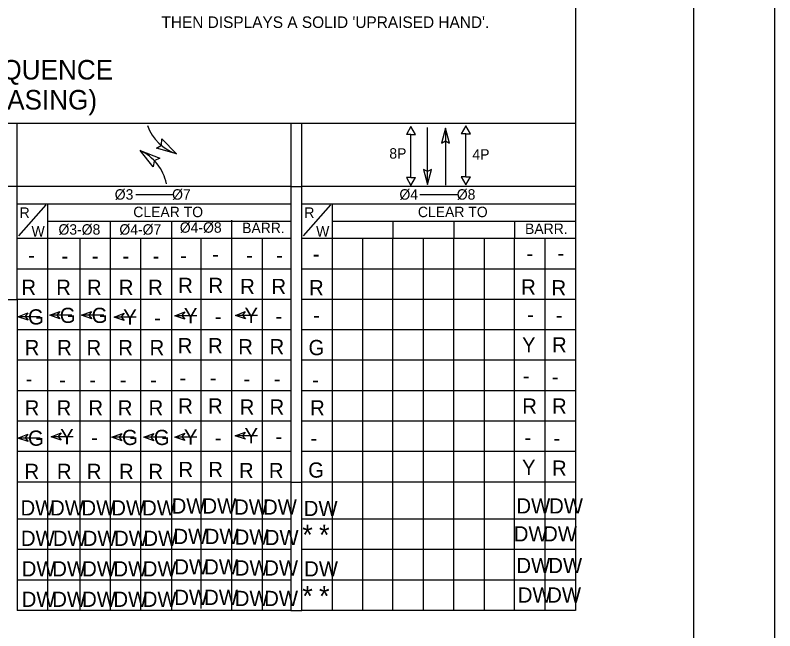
# Model space of a CAD drawing. Extents: x 0 to 3.01, y -0.05 to 1.83.
# Drawn here: x 2.6475 to 3, y 1.2662 to 1.5516 of the extents above; entities that cross this region are included whole.
import ezdxf

# ---------------------------------------------------------------- set-up
doc = ezdxf.new("R2010")
doc.units = 0
for name, color, linetype in [('RD_SHT_IplotShp', 7, 'Continuous'), ('TR_TS_Border', 7, 'Continuous'), ('TR_TS_Phase1', 7, 'Continuous'), ('TR_TS_Phase2', 7, 'Continuous'), ('TR_TS_Phase3', 7, 'Continuous'), ('TR_TS_Phase4', 7, 'Continuous'), ('TR_TS_Phase5', 7, 'Continuous'), ('TR_TS_Phase6', 7, 'Continuous'), ('TR_TS_Phase7', 7, 'Continuous'), ('TR_TS_Phase8', 7, 'Continuous')]:
    doc.layers.add(name, color=color, linetype=linetype)

msp = doc.modelspace()

# ---------------------------------------------------------------- linework, layer by layer
at = {"layer": 'RD_SHT_IplotShp'}
msp.add_lwpolyline([(-3.9736429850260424e-10, -8.265177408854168e-09), (3.0000020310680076, -8.265177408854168e-09), (3.0000020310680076, 1.8333311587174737), (-3.9736429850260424e-10, 1.8333311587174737)], close=True, dxfattribs=at)
at = {"layer": 'TR_TS_Border'}
for p, q in [((3.0000020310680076, -8.265177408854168e-09), (3.0000020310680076, 1.8333311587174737)), ((2.9623464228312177, 0.04746643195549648), (2.9623464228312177, 1.775395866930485)), ((2.9074767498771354, 1.7049511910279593), (2.9074766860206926, 1.275593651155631)), ((2.907476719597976, 1.5013454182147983), (2.2983738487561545, 1.5013454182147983)), ((2.6483232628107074, 1.4198639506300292), (2.6483232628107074, 1.5013455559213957)), ((2.7753427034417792, 1.5013455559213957), (2.7753427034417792, 1.27559374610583)), ((2.780404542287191, 1.5013455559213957), (2.780404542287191, 1.27559374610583)), ((2.6483232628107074, 1.4722744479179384), (2.638252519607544, 1.4722744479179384)), ((2.7753427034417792, 1.4722744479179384), (2.6483232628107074, 1.4722744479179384)), ((2.7753427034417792, 1.4722744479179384), (2.780404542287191, 1.4722744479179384)), ((2.907476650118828, 1.4722744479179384), (2.780404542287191, 1.4722744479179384)), ((2.7034480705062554, 1.468530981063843), (2.7205960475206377, 1.468530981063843)), ((2.8352356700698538, 1.468530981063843), (2.8529832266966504, 1.468530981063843)), ((2.6483232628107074, 1.4642071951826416), (2.7753427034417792, 1.4642071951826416)), ((2.649167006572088, 1.4492854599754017), (2.661821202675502, 1.4637328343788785)), ((2.6624014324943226, 1.4642071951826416), (2.6624014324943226, 1.27559374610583)), ((2.780404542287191, 1.4642071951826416), (2.907476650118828, 1.4642071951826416)), ((2.781248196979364, 1.4492854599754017), (2.7939024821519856, 1.4637328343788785)), ((2.794535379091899, 1.4642071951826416), (2.794535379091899, 1.27559374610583)), ((2.6624014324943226, 1.4561402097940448), (2.7753427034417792, 1.4561402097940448)), ((2.6915352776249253, 1.4561402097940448), (2.6915352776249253, 1.27559374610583)), ((2.720037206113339, 1.4562394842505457), (2.720037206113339, 1.2756930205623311)), ((2.7479278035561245, 1.4565373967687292), (2.7479278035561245, 1.275990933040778)), ((2.794535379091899, 1.4561402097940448), (2.907476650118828, 1.4561402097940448)), ((2.8227442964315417, 1.4561402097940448), (2.8227442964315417, 1.4480727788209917)), ((2.8510059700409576, 1.4561402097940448), (2.8510059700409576, 1.4480727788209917)), ((2.8792152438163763, 1.4561402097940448), (2.8792152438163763, 1.4480727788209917)), ((2.7753427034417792, 1.4480727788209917), (2.6483232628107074, 1.4480727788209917)), ((2.6774043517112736, 1.4480727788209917), (2.6774043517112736, 1.27559374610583)), ((2.7056134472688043, 1.4480727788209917), (2.7056134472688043, 1.27559374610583)), ((2.7336929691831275, 1.4480727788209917), (2.7336929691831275, 1.276487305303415)), ((2.7620583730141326, 1.4480727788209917), (2.7620583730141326, 1.275990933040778)), ((2.907476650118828, 1.4480727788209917), (2.780404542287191, 1.4480727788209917)), ((2.808666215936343, 1.4480727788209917), (2.808666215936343, 1.27559374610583)), ((2.8227442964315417, 1.27559374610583), (2.8227442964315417, 1.4480727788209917)), ((2.8368751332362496, 1.4480727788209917), (2.8368751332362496, 1.27559374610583)), ((2.8510059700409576, 1.27559374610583), (2.8510059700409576, 1.4480727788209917)), ((2.8651368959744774, 1.4480727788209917), (2.8651368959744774, 1.27559374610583)), ((2.8792152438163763, 1.27559374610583), (2.8792152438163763, 1.4480727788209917)), ((2.89334572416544, 1.4480727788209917), (2.89334572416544, 1.27559374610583)), ((2.7753427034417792, 1.433941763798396), (2.6483232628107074, 1.433941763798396)), ((2.907476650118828, 1.433941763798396), (2.780404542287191, 1.433941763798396)), ((2.638252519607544, 1.4198639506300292), (2.6483232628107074, 1.4198639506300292)), ((2.7753427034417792, 1.4198639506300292), (2.6483232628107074, 1.4198639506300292)), ((2.6483232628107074, 1.4198639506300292), (2.6483232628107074, 1.27559374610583)), ((2.907476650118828, 1.4198639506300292), (2.780404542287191, 1.4198639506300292)), ((2.7753427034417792, 1.405733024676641), (2.6483232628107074, 1.405733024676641)), ((2.907476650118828, 1.405733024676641), (2.780404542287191, 1.405733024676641)), ((2.7753427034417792, 1.3916020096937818), (2.6483232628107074, 1.3916020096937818)), ((2.907476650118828, 1.3916020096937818), (2.780404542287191, 1.3916020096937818)), ((2.7753427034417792, 1.3775241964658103), (2.6483232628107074, 1.3775241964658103)), ((2.907476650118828, 1.3775241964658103), (2.780404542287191, 1.3775241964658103)), ((2.7753427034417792, 1.3633932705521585), (2.6483232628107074, 1.3633932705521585)), ((2.907476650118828, 1.3633932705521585), (2.780404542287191, 1.3633932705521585)), ((2.7753427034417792, 1.3492622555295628), (2.6483232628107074, 1.3492622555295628)), ((2.907476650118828, 1.3492622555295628), (2.780404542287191, 1.3492622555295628)), ((2.7753427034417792, 1.3351314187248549), (2.6483232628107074, 1.3351314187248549)), ((2.7753427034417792, 1.3351314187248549), (2.780404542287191, 1.3351314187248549)), ((2.907476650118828, 1.3351314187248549), (2.780404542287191, 1.3351314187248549)), ((2.775416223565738, 1.3179863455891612), (2.6483966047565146, 1.3179863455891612)), ((2.9075500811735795, 1.3179863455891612), (2.780477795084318, 1.3179863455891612)), ((2.775416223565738, 1.3038554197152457), (2.6483966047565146, 1.3038554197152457)), ((2.9075500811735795, 1.3038554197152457), (2.780477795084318, 1.3038554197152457)), ((2.775416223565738, 1.2897245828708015), (2.6483966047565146, 1.2897245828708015)), ((2.9075500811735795, 1.2897245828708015), (2.780477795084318, 1.2897245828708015)), ((2.775416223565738, 1.27559374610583), (2.6483966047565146, 1.27559374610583)), ((2.775416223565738, 1.27559374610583), (2.780477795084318, 1.27559374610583)), ((2.907476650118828, 1.27559374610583), (2.780477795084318, 1.27559374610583))]:
    msp.add_line(p, q, dxfattribs=at)
at = {"layer": 'TR_TS_Phase3'}
for p, q in [((2.7129855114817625, 1.489924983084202), (2.7153600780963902, 1.4914362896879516)), ((2.7153600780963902, 1.4914362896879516), (2.715504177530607, 1.4942426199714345)), ((2.715504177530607, 1.4942426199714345), (2.722340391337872, 1.4874063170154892)), ((2.722340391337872, 1.4874063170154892), (2.7129855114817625, 1.489924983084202)), ((2.6634985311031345, 1.4125119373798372), (2.6681329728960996, 1.4142745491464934)), ((2.6681329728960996, 1.4142745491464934), (2.6668036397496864, 1.4125706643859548)), ((2.67829194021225, 1.4125119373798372), (2.6829263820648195, 1.4142745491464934)), ((2.6829263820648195, 1.4142745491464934), (2.681597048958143, 1.4125706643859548)), ((2.7215234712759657, 1.412266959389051), (2.726157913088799, 1.4140297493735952)), ((2.726157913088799, 1.4140297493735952), (2.7248285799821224, 1.4123256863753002)), ((2.7496479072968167, 1.412454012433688), (2.754282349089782, 1.4142166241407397)), ((2.754282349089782, 1.4142166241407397), (2.7529530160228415, 1.4125127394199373)), ((2.6487489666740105, 1.4117958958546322), (2.6533833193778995, 1.4135586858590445)), ((2.659010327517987, 1.4117958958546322), (2.6487489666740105, 1.4117958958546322)), ((2.6534273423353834, 1.4101873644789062), (2.6487489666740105, 1.4117958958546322)), ((2.6533833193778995, 1.4135586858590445), (2.6520540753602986, 1.4118546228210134)), ((2.6520540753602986, 1.4118546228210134), (2.6534273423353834, 1.4101873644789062)), ((2.6737599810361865, 1.4125119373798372), (2.6634985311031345, 1.4125119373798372)), ((2.6681769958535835, 1.4109034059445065), (2.6634985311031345, 1.4125119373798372)), ((2.6668036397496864, 1.4125706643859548), (2.6681769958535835, 1.4109034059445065)), ((2.6885533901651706, 1.4125119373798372), (2.67829194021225, 1.4125119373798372)), ((2.682970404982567, 1.4109034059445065), (2.67829194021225, 1.4125119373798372)), ((2.681597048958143, 1.4125706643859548), (2.682970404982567, 1.4109034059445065)), ((2.6933708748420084, 1.4116336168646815), (2.6980052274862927, 1.4133964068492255)), ((2.7036318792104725, 1.4116336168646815), (2.6933708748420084, 1.4116336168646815)), ((2.698049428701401, 1.4100252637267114), (2.6933708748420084, 1.4116336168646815)), ((2.6980052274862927, 1.4133964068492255), (2.6966759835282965, 1.4116924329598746)), ((2.6966759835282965, 1.4116924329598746), (2.698049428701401, 1.4100252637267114)), ((2.7317845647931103, 1.412266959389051), (2.7215234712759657, 1.412266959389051)), ((2.726201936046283, 1.410658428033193), (2.7215234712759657, 1.412266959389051)), ((2.7248285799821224, 1.4123256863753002), (2.726201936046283, 1.410658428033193)), ((2.759909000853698, 1.412454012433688), (2.7496479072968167, 1.412454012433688)), ((2.7543263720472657, 1.4108454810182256), (2.7496479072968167, 1.412454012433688)), ((2.7529530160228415, 1.4125127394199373), (2.7543263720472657, 1.4108454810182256))]:
    msp.add_line(p, q, dxfattribs=at)
msp.add_arc((2.729174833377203, 1.5078541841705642), 0.021617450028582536, 200.13881944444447, 251.63656666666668, dxfattribs=at)
at = {"layer": 'TR_TS_Phase4'}
for p, q in [((2.847129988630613, 1.499277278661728), (2.8452641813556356, 1.4923477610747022)), ((2.847129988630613, 1.499277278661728), (2.847129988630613, 1.4728914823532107)), ((2.8489957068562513, 1.4923477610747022), (2.847129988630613, 1.499277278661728)), ((2.856627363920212, 1.5003211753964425), (2.854495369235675, 1.4966489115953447)), ((2.858759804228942, 1.4966489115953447), (2.856627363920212, 1.5003211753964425)), ((2.856627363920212, 1.4966489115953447), (2.854495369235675, 1.4966489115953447)), ((2.856627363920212, 1.4766825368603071), (2.856627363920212, 1.4966489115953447)), ((2.856627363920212, 1.4966489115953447), (2.858759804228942, 1.4966489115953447)), ((2.8452641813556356, 1.4923477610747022), (2.847129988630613, 1.4933072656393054)), ((2.847129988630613, 1.4933072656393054), (2.8489957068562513, 1.4923477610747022)), ((2.856627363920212, 1.4766110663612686), (2.8544951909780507, 1.4766110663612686)), ((2.8544951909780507, 1.4766110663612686), (2.856627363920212, 1.4729388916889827)), ((2.856627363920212, 1.4729388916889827), (2.8587596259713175, 1.4766110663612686)), ((2.856627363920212, 1.4766110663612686), (2.8587596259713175, 1.4766110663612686))]:
    msp.add_line(p, q, dxfattribs=at)
at = {"layer": 'TR_TS_Phase7'}
for p, q in [((2.7115733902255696, 1.4813676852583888), (2.7055217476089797, 1.4889076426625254)), ((2.7055217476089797, 1.4889076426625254), (2.714546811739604, 1.4853856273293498)), ((2.7120218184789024, 1.4841416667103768), (2.7115733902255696, 1.4813676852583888)), ((2.714546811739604, 1.4853856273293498), (2.7120218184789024, 1.4841416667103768)), ((2.6487489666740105, 1.355571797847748), (2.6533833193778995, 1.3573344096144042)), ((2.6533833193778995, 1.3573344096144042), (2.6520540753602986, 1.3556305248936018)), ((2.6641120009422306, 1.3561904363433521), (2.668746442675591, 1.3579530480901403)), ((2.668746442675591, 1.3579530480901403), (2.6674171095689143, 1.3562492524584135)), ((2.692367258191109, 1.3558971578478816), (2.697001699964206, 1.357659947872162)), ((2.697001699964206, 1.357659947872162), (2.6956723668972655, 1.355955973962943)), ((2.707160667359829, 1.3558971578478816), (2.711795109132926, 1.357659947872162)), ((2.711795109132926, 1.357659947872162), (2.710465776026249, 1.355955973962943)), ((2.7215234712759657, 1.356042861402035), (2.726157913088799, 1.3578054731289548)), ((2.726157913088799, 1.3578054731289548), (2.7248285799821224, 1.356101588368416)), ((2.7496428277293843, 1.3565876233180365), (2.7542772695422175, 1.3583502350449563)), ((2.7542772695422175, 1.3583502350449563), (2.752947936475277, 1.3566464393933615)), ((2.659010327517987, 1.355571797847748), (2.6487489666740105, 1.355571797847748)), ((2.6534273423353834, 1.3539632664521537), (2.6487489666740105, 1.355571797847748)), ((2.6520540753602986, 1.3556305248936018), (2.6534273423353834, 1.3539632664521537)), ((2.6743730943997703, 1.3561904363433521), (2.6641120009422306, 1.3561904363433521)), ((2.6687904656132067, 1.3545819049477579), (2.6641120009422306, 1.3561904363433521)), ((2.6674171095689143, 1.3562492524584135), (2.6687904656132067, 1.3545819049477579)), ((2.7026287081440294, 1.3558971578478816), (2.692367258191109, 1.3558971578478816)), ((2.6970457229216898, 1.3542886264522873), (2.692367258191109, 1.3558971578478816)), ((2.6956723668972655, 1.355955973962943), (2.6970457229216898, 1.3542886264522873)), ((2.717421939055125, 1.3558971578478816), (2.707160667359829, 1.3558971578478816)), ((2.711839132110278, 1.3542886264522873), (2.707160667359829, 1.3558971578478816)), ((2.710465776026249, 1.355955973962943), (2.711839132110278, 1.3542886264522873)), ((2.7317845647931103, 1.356042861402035), (2.7215234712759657, 1.356042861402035)), ((2.726201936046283, 1.3544343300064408), (2.7215234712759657, 1.356042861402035)), ((2.7248285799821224, 1.356101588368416), (2.726201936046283, 1.3544343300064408)), ((2.7599039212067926, 1.3565876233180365), (2.7496428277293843, 1.3565876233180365)), ((2.7543214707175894, 1.3549790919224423), (2.7496428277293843, 1.3565876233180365)), ((2.752947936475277, 1.3566464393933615), (2.7543214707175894, 1.3549790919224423))]:
    msp.add_line(p, q, dxfattribs=at)
msp.add_arc((2.6964534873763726, 1.4692224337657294), 0.02161745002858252, 11.426533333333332, 65.38743333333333, dxfattribs=at)
at = {"layer": 'TR_TS_Phase8'}
for p, q in [((2.831158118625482, 1.5000583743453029), (2.8290260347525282, 1.4963861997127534)), ((2.8332904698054, 1.4963861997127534), (2.831158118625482, 1.5000583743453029)), ((2.8388868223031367, 1.4731735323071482), (2.8388868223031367, 1.4995593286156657)), ((2.831158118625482, 1.4963861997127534), (2.8290260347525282, 1.4963861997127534)), ((2.831158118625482, 1.476419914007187), (2.831158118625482, 1.4963861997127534)), ((2.831158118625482, 1.4963861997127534), (2.8332904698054, 1.4963861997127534)), ((2.8388868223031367, 1.4791435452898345), (2.837021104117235, 1.4801030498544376)), ((2.837021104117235, 1.4801030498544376), (2.8388868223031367, 1.4731735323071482)), ((2.8407525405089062, 1.4801030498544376), (2.8388868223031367, 1.4791435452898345)), ((2.8388868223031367, 1.4731735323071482), (2.8407525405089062, 1.4801030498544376)), ((2.831158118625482, 1.4763484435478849), (2.8290258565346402, 1.4763484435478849)), ((2.8290258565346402, 1.4763484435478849), (2.831158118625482, 1.4726762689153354)), ((2.831158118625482, 1.4726762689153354), (2.833290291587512, 1.4763484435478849)), ((2.831158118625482, 1.4763484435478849), (2.833290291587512, 1.4763484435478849))]:
    msp.add_line(p, q, dxfattribs=at)

# ---------------------------------------------------------------- texts
at = {"layer": 'TR_TS_Border'}
for s, height, p in [("THEN DISPLAYS A SOLID 'UPRAISED HAND'.", 0.005346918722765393, (2.7153579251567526, 1.5457078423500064)), ('SIGNAL DISPLAY SEQUENCE', 0.009062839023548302, (2.5225272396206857, 1.5218125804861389)), ('(PREFERENTIAL PHASING)', 0.009062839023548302, (2.5279138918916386, 1.5078981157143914))]:
    msp.add_text(s, height=height, dxfattribs=at).set_placement(p)
for s, height, p in [('Ø3          Ø7', 0.004840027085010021, (2.6936825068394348, 1.466104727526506)), ('Ø4          Ø8', 0.004840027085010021, (2.8258007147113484, 1.466104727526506)), ('R', 0.004840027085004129, (2.6495210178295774, 1.457668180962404)), ('CLEAR TO', 0.004840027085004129, (2.702291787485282, 1.4579846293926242)), ('R', 0.004840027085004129, (2.7816552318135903, 1.457668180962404)), ('CLEAR TO', 0.004840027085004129, (2.8343729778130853, 1.4579846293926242)), ('W', 0.004840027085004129, (2.6550681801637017, 1.4489682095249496)), ('Ø3-Ø8', 0.004840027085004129, (2.6675674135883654, 1.4498646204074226)), ('Ø4-Ø7', 0.004840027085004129, (2.695846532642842, 1.4498646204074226)), ('Ø4-Ø8', 0.004840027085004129, (2.723873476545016, 1.4507581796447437)), ('BARR.', 0.004840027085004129, (2.7528034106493, 1.4505781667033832)), ('W', 0.004840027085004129, (2.7871494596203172, 1.4489682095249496)), ('BARR.', 0.004840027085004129, (2.8840906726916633, 1.4501810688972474))]:
    msp.add_text(s, height=height, rotation=360, dxfattribs=at).set_placement(p)
at = {"layer": 'TR_TS_Phase1'}
for p in [(2.6534825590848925, 1.4368748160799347), (2.668997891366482, 1.436473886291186), (2.683032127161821, 1.436473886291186), (2.6972190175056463, 1.436473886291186), (2.711253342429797, 1.436473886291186), (2.7239767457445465, 1.4367453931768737), (2.7389060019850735, 1.437367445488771), (2.7545894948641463, 1.4368709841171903), (2.7686236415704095, 1.4368709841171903), (2.7856278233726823, 1.4374106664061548), (2.8847434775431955, 1.4375876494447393), (2.899194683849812, 1.43781346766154)]:
    msp.add_text('-', height=0.007050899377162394, dxfattribs=at).set_placement(p)
at = {"layer": 'TR_TS_Phase2'}
for s, p in [('R', (2.6503341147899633, 1.4219349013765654)), ('R', (2.6664964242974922, 1.4219349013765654)), ('R', (2.6807937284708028, 1.4219349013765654)), ('R', (2.695531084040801, 1.4219349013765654)), ('R', (2.7091685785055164, 1.4219349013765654)), ('R', (2.723111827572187, 1.4228284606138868)), ('R', (2.7371892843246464, 1.4228284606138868)), ('R', (2.7518692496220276, 1.4223319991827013)), ('R', (2.7663863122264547, 1.4223319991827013)), ('DW', (2.6499532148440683, 1.3196504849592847)), ('DW', (2.6636959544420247, 1.3196504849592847)), ('DW', (2.6782131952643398, 1.3196504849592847)), ('DW', (2.692070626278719, 1.3196504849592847)), ('DW', (2.7063679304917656, 1.3196504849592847)), ('DW', (2.7200915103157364, 1.3205440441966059)), ('DW', (2.7343888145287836, 1.3205440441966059)), ('DW', (2.749068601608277, 1.3200475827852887)), ('DW', (2.762485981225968, 1.3200475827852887)), ('DW', (2.7814003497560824, 1.3193922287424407)), ('DW', (2.8800810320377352, 1.320579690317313)), ('DW', (2.8952685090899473, 1.320579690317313))]:
    msp.add_text(s, height=0.007050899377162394, dxfattribs=at).set_placement(p)
for p in [(2.783835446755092, 1.4217815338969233), (2.882265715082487, 1.4220936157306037), (2.89634531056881, 1.4217198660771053)]:
    msp.add_text('R', height=0.007050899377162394, rotation=360, dxfattribs=at).set_placement(p)
at = {"layer": 'TR_TS_Phase3'}
for s, p in [('G', (2.653425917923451, 1.4082141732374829)), ('G', (2.6681756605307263, 1.4089298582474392)), ('G', (2.6829690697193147, 1.4089298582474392)), ('Y', (2.6976008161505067, 1.4081451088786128)), ('Y', (2.7257530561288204, 1.4087780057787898)), ('Y', (2.7538776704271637, 1.4089649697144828)), ('-', (2.7119710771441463, 1.4077913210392)), ('-', (2.740123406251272, 1.4084243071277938)), ('-', (2.768247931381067, 1.4086112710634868)), ('-', (2.785681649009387, 1.4089818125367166)), ('-', (2.884998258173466, 1.4093655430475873)), ('-', (2.8984195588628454, 1.4089818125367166))]:
    msp.add_text(s, height=0.007050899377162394, dxfattribs=at).set_placement(p)
at = {"layer": 'TR_TS_Phase4'}
for s, height, p in [('4P', 0.004840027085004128, (2.859666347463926, 1.4846578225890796)), ('R', 0.007050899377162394, (2.651873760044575, 1.3939847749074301)), ('R', 0.007050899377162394, (2.666936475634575, 1.3939847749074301)), ('R', 0.007050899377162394, (2.6805739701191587, 1.3939847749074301)), ('R', 0.007050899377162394, (2.695311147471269, 1.3939847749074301)), ('R', 0.007050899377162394, (2.709828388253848, 1.3939847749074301)), ('R', 0.007050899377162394, (2.7228919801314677, 1.3948783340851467)), ('R', 0.007050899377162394, (2.7369693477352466, 1.3948783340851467)), ('R', 0.007050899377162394, (2.7509895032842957, 1.3943818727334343)), ('R', 0.007050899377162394, (2.7655067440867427, 1.3943818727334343)), ('*', 0.009384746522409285, (2.7807040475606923, 1.306046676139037)), ('*', 0.009384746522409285, (2.78847454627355, 1.3059902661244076)), ('DW', 0.007050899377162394, (2.650135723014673, 1.3055341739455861)), ('DW', 0.007050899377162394, (2.664957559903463, 1.3055341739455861)), ('DW', 0.007050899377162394, (2.67881499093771, 1.3055341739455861)), ('DW', 0.007050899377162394, (2.693332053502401, 1.3055341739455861)), ('DW', 0.007050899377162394, (2.7069695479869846, 1.3055341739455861)), ('DW', 0.007050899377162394, (2.7209339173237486, 1.3064277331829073)), ('DW', 0.007050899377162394, (2.735430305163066, 1.3064277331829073)), ('DW', 0.007050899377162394, (2.74930502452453, 1.3061141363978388)), ('DW', 0.007050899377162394, (2.763307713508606, 1.3059312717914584)), ('DW', 0.007050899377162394, (2.8788583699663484, 1.307618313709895)), ('DW', 0.007050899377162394, (2.8924881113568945, 1.307618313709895))]:
    msp.add_text(s, height=height, dxfattribs=at).set_placement(p)
for s, p in [('G', (2.783614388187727, 1.3939964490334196)), ('Y', (2.8826887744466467, 1.3952718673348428)), ('R', (2.8966079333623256, 1.3952718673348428))]:
    msp.add_text(s, height=0.007050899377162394, rotation=360, dxfattribs=at).set_placement(p)
at = {"layer": 'TR_TS_Phase5'}
for p in [(2.6523123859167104, 1.379479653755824), (2.667827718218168, 1.3790785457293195), (2.681861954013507, 1.3790785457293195), (2.6960486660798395, 1.3790785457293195), (2.7100828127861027, 1.3790785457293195), (2.72370150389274, 1.3799721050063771), (2.737735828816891, 1.3799721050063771), (2.7534193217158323, 1.37947564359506), (2.767453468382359, 1.37947564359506), (2.785237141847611, 1.3790879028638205), (2.8830474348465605, 1.3808629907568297), (2.896468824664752, 1.380479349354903)]:
    msp.add_text('-', height=0.007050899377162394, dxfattribs=at).set_placement(p)
at = {"layer": 'TR_TS_Phase6'}
for s, p in [('R', (2.651873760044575, 1.366034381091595)), ('R', (2.666716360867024, 1.366034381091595)), ('R', (2.6814536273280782, 1.366034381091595)), ('R', (2.6950910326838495, 1.366034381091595)), ('R', (2.709388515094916, 1.366034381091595)), ('R', (2.723111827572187, 1.3669279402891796)), ('R', (2.7369691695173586, 1.3669279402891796)), ('R', (2.751649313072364, 1.3664314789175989)), ('R', (2.7655067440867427, 1.3664314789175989)), ('DW', (2.650500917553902, 1.2914032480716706)), ('DW', (2.6646837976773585, 1.2914032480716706)), ('DW', (2.678541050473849, 1.2914032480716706)), ('DW', (2.69305829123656, 1.2914032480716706)), ('DW', (2.7066957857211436, 1.2914032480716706)), ('DW', (2.721299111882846, 1.2922968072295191)), ('DW', (2.735156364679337, 1.2922968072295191)), ('DW', (2.749396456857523, 1.2918003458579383)), ('DW', (2.7630338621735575, 1.2918003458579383)), ('DW', (2.781583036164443, 1.291381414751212)), ('DW', (2.8800810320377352, 1.2929342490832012)), ('DW', (2.894878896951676, 1.2929342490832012))]:
    msp.add_text(s, height=0.007050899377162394, dxfattribs=at).set_placement(p)
for p in [(2.784319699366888, 1.366062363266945), (2.8827907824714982, 1.3668740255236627), (2.8966079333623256, 1.3668740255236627)]:
    msp.add_text('R', height=0.007050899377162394, rotation=360, dxfattribs=at).set_placement(p)
at = {"layer": 'TR_TS_Phase7'}
for s, p in [('G', (2.653425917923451, 1.3519898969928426)), ('Y', (2.6683417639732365, 1.3527018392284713)), ('G', (2.6970447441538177, 1.352315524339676)), ('G', (2.71183815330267, 1.352315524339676)), ('Y', (2.7257530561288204, 1.3525540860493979)), ('Y', (2.7538729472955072, 1.3530989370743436)), ('-', (2.682712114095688, 1.3523481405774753)), ('-', (2.740123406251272, 1.352200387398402)), ('-', (2.768243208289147, 1.3527452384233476)), ('-', (2.7845111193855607, 1.3519767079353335)), ('-', (2.8838278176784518, 1.35236034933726)), ('-', (2.897249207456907, 1.3519767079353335))]:
    msp.add_text(s, height=0.007050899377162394, dxfattribs=at).set_placement(p)
at = {"layer": 'TR_TS_Phase8'}
for s, height, p in [('8P', 0.004840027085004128, (2.8211102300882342, 1.4851099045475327)), ('R', 0.007050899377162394, (2.651782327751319, 1.3365856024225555)), ('R', 0.007050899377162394, (2.666844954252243, 1.3365856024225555)), ('R', 0.007050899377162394, (2.6807022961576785, 1.3365856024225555)), ('R', 0.007050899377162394, (2.695659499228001, 1.3365856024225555)), ('R', 0.007050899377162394, (2.7092969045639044, 1.3365856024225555)), ('R', 0.007050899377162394, (2.7232403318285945, 1.3374791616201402)), ('R', 0.007050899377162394, (2.7370977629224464, 1.3374791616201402)), ('R', 0.007050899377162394, (2.7513377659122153, 1.3369827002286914)), ('R', 0.007050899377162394, (2.7651950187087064, 1.3369827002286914)), ('*', 0.009384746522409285, (2.7807040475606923, 1.2776409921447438)), ('*', 0.009384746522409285, (2.78847454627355, 1.277584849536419)), ('DW', 0.007050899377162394, (2.650500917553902, 1.2772724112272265)), ('DW', 0.007050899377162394, (2.6646837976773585, 1.2772724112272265)), ('DW', 0.007050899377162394, (2.678541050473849, 1.2772724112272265)), ('DW', 0.007050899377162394, (2.69305829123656, 1.2772724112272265)), ('DW', 0.007050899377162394, (2.7066957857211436, 1.2772724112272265)), ('DW', 0.007050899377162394, (2.721299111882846, 1.2781659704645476)), ('DW', 0.007050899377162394, (2.735156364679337, 1.2781659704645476)), ('DW', 0.007050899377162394, (2.749396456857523, 1.2776695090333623)), ('DW', 0.007050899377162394, (2.7630338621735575, 1.2776695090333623)), ('DW', 0.007050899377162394, (2.8807432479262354, 1.2792554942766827)), ('DW', 0.007050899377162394, (2.894372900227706, 1.2792554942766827))]:
    msp.add_text(s, height=height, dxfattribs=at).set_placement(p)
for s, p in [('G', (2.783465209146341, 1.3371972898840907)), ('Y', (2.8826887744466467, 1.3384760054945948)), ('R', (2.8966079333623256, 1.3381023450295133))]:
    msp.add_text(s, height=0.007050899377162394, rotation=360, dxfattribs=at).set_placement(p)

doc.saveas('drawing.dxf')
